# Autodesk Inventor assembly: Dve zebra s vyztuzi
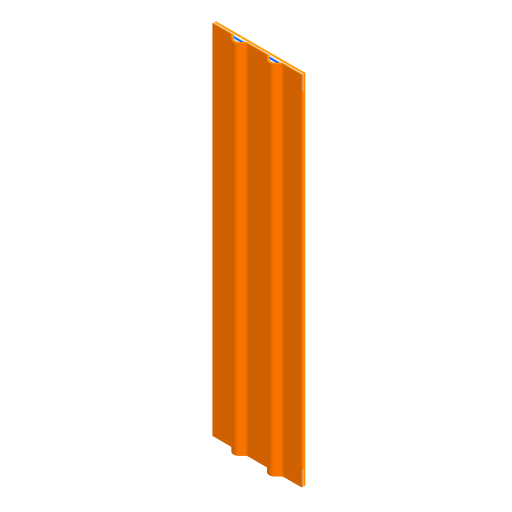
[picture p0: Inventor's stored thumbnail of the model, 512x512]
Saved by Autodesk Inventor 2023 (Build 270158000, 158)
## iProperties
Created: 2025-03
Part Number: Dve zebra s vyztuzi
Document SubType Name: Assembly
Designer: tomik
Author: tomik
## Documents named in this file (5)
- C:\Users\tomik\Desktop\Diplomka\Struktury\Desky\Struktury_20.3\Dvě žebra s výztuží\Dve zebra s vyztuzi.iam
- C:\Users\tomik\Desktop\Diplomka\Struktury\Desky\Struktury_20.3\Dvě žebra s výztuží\Spodni tkanina 50x200.ipt
- C:\Users\tomik\Desktop\Diplomka\Struktury\Desky\Struktury_20.3\Dvě žebra s výztuží\Zebro s vyztuhou .ipt
- C:\Users\tomik\Desktop\Diplomka\Struktury\Desky\Struktury_20.3\Dvě žebra s výztuží\Vyztuha.ipt
- C:\Users\tomik\Desktop\Diplomka\Struktury\Desky\Struktury_20.3\Dvě žebra s výztuží\Horni tkanina.ipt
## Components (5 placed, 4 different names)
1. Spodni tkanina 50x200:1 — Proti sobě:1, Proti sobě:2, Stejný směr:1, Proti sobě:11, Proti sobě:13, Proti sobě:20, Proti sobě:21
2. Zebro s vyztuhou :1 — Proti sobě:11, Proti sobě:13, Proti sobě:14, Proti sobě:15, Proti sobě:16, Proti sobě:17, Proti sobě:18, Proti sobě:19, Proti sobě:22
3. Vyztuha:1 — Proti sobě:14, Proti sobě:15, Proti sobě:16
4. Vyztuha:2 — Proti sobě:17, Proti sobě:18, Proti sobě:19
5. Horni tkanina:1 — Proti sobě:20, Proti sobě:21, Proti sobě:22
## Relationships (14: Mate 13, Flush 1)
- Proti sobě:1 [Mate]: Spodni tkanina 50x200:1
- Proti sobě:2 [Mate]: Spodni tkanina 50x200:1
- Stejný směr:1 [Flush]: Spodni tkanina 50x200:1
- Proti sobě:11 [Mate]: Spodni tkanina 50x200:1 ↔ Zebro s vyztuhou :1
- Proti sobě:13 [Mate]: Spodni tkanina 50x200:1 ↔ Zebro s vyztuhou :1
- Proti sobě:14 [Mate]: Zebro s vyztuhou :1 ↔ Vyztuha:1
- Proti sobě:15 [Mate]: Zebro s vyztuhou :1 ↔ Vyztuha:1
- Proti sobě:16 [Mate]: Zebro s vyztuhou :1 ↔ Vyztuha:1
- Proti sobě:17 [Mate]: Zebro s vyztuhou :1 ↔ Vyztuha:2
- Proti sobě:18 [Mate]: Zebro s vyztuhou :1 ↔ Vyztuha:2
- Proti sobě:19 [Mate]: Zebro s vyztuhou :1 ↔ Vyztuha:2
- Proti sobě:20 [Mate]: Spodni tkanina 50x200:1 ↔ Horni tkanina:1
- Proti sobě:21 [Mate]: Spodni tkanina 50x200:1 ↔ Horni tkanina:1
- Proti sobě:22 [Mate]: Zebro s vyztuhou :1 ↔ Horni tkanina:1
